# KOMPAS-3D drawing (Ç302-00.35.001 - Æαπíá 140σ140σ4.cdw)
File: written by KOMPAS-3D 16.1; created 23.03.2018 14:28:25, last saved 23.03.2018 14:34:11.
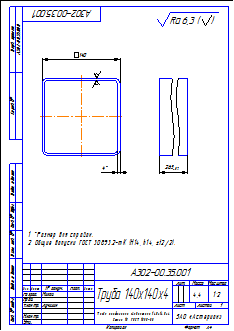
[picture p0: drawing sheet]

Sheet 1: A4, portrait

Title block, sheet 1: name: Труба 140х140х4; designation: А302-00.35.001; mass: 4,4; scale: 1:2; sheets: 1; organisation: ЗАО «Астерион»; sheet format: A4; stored path: \\192.168.87.28\Konstructor_doc\Мембранные насосы\Мембранный электропривод\А302-00.00.000 - ASTRA-302 (МЭ200)\Чертежи\А302-00.35.001 - Труба 140х140х4.cdw; drawn by: Милов; technical control: Лучихин

Views: Вид 1, Спереди, Проекционный вид 2
Referenced files in Z:\Мембранные насосы\Мембранный электропривод\А302-00.00.000 - ASTRA-302 (МЭ200)\3Д\: А302-00.35.001 - Труба 140х140х4.m3d
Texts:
  Труба профильная квадратная 140х140х4
  *Размер для справок.
  Общие допуски ГОСТ 30893.2-mK (H14, h14,  t2/2).
  Ra 6,3
  Ra 6,3 ( )
Dimensions and other numbers on the sheet: 140; 4; 265; 1:2; 1; 4,4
